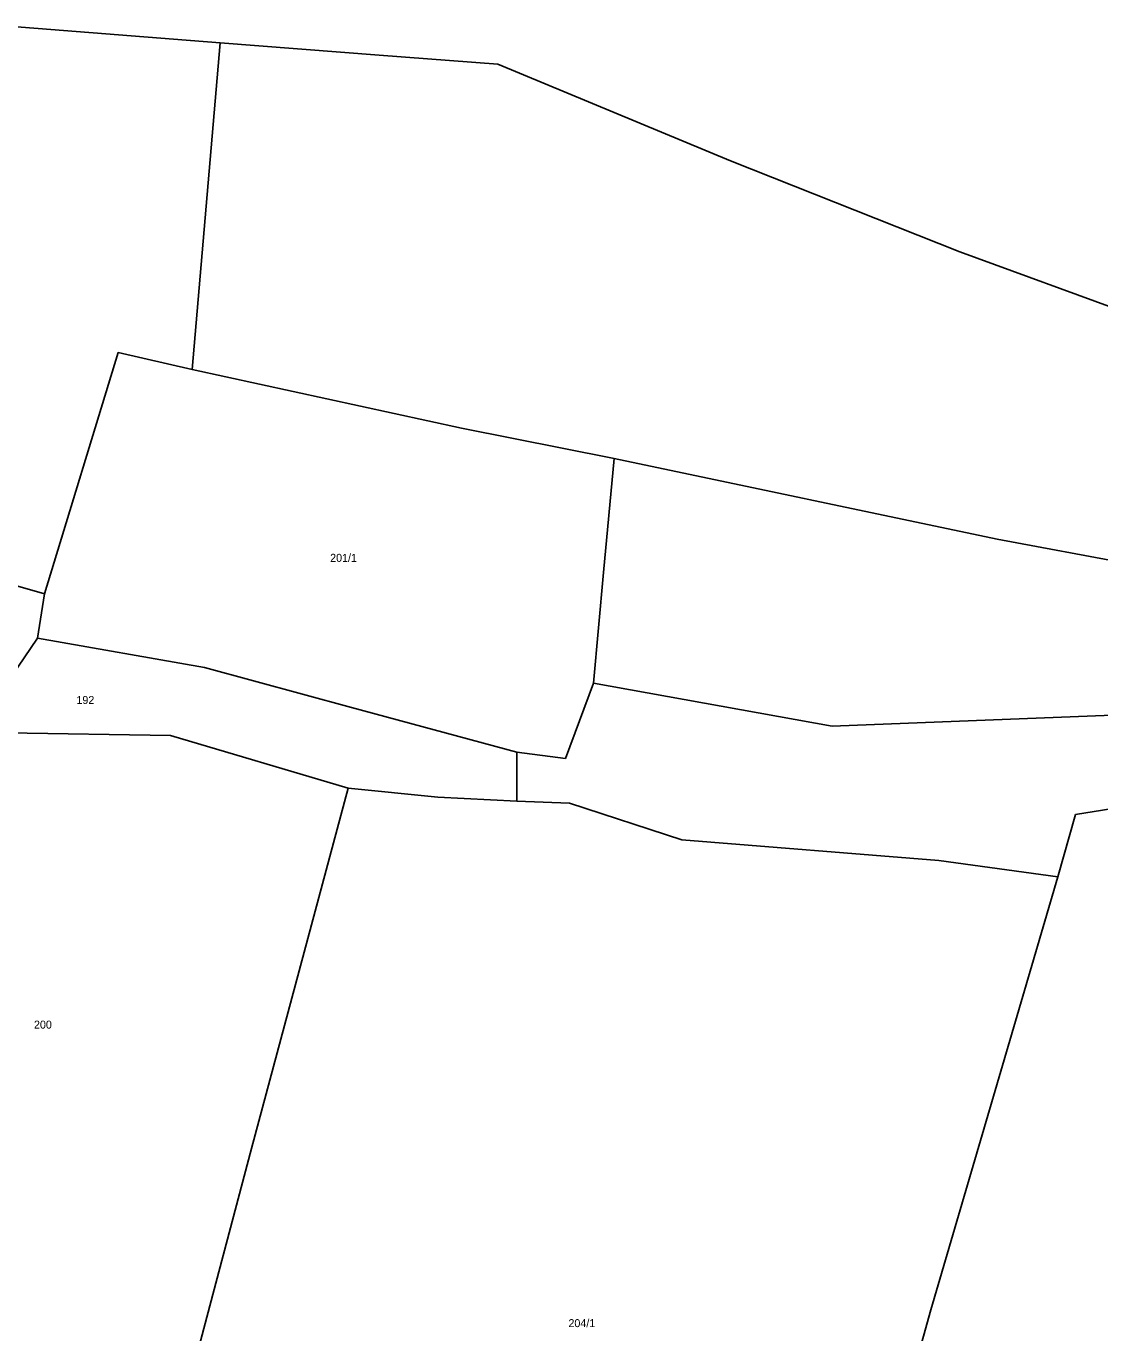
# Model space of a CAD drawing. Extents: x -791548 to -789311, y -1142631 to -1140855.
# Drawn here: x -790605.8 to -790377.8, y -1141528.8 to -1141251.3 of the extents above; entities that cross this region are included whole.
import ezdxf
from ezdxf.enums import TextEntityAlignment as Align

# ---------------------------------------------------------------- set-up
doc = ezdxf.new("R2010")
doc.units = 0
doc.header["$LTSCALE"] = 0.68
doc.layers.add('1', color=7, linetype='Continuous', lineweight=25)
doc.layers.add('2', color=7, linetype='Continuous')

msp = doc.modelspace()

# ---------------------------------------------------------------- linework, layer by layer
at = {"layer": '1'}
for p, q in [((-790574.52, -1141254.07), (-790609.55, -1141251.27)), ((-790574.52, -1141254.07), (-790564.64, -1141254.83)), ((-790570.59, -1141324.19), (-790564.64, -1141254.83)), ((-790564.64, -1141254.83), (-790530.84, -1141257.42)), ((-790505.62, -1141259.33), (-790530.84, -1141257.42)), ((-790456.26, -1141279.85), (-790505.62, -1141259.33)), ((-790407.51, -1141299.23), (-790456.26, -1141279.85)), ((-790322.4, -1141330.26), (-790407.51, -1141299.23)), ((-790601.94, -1141371.83), (-790586.26, -1141320.61)), ((-790586.26, -1141320.61), (-790570.59, -1141324.19)), ((-790513.36, -1141336.67), (-790570.59, -1141324.19)), ((-790480.92, -1141343.07), (-790513.36, -1141336.67)), ((-790483.19, -1141367.29), (-790480.92, -1141343.07)), ((-790399.6, -1141360.25), (-790480.92, -1141343.07)), ((-790335.65, -1141372.07), (-790399.6, -1141360.25)), ((-790601.94, -1141371.83), (-790626.13, -1141364.99)), ((-790485.29, -1141390.8), (-790483.19, -1141367.29)), ((-790603.44, -1141381.28), (-790601.94, -1141371.83)), ((-790611.73, -1141393.4), (-790603.44, -1141381.28)), ((-790567.95, -1141387.46), (-790603.44, -1141381.28)), ((-790536.74, -1141395.99), (-790567.95, -1141387.46)), ((-790491.26, -1141406.79), (-790485.29, -1141390.8)), ((-790485.29, -1141390.8), (-790434.62, -1141399.94)), ((-790501.59, -1141405.51), (-790536.74, -1141395.99)), ((-790434.62, -1141399.94), (-790344.25, -1141396.36)), ((-790609.89, -1141401.37), (-790575.13, -1141401.94)), ((-790575.13, -1141401.94), (-790537.46, -1141413.13)), ((-790501.6, -1141415.91), (-790501.59, -1141405.51)), ((-790501.59, -1141405.51), (-790491.26, -1141406.79)), ((-790557.94, -1141489.62), (-790537.46, -1141413.13)), ((-790537.46, -1141413.13), (-790518.37, -1141415.04)), ((-790518.37, -1141415.04), (-790501.6, -1141415.91)), ((-790490.42, -1141416.31), (-790501.6, -1141415.91)), ((-790466.55, -1141424.12), (-790490.42, -1141416.31)), ((-790369.23, -1141416.5), (-790382.93, -1141418.73)), ((-790382.93, -1141418.73), (-790386.72, -1141431.98)), ((-790412.01, -1141428.45), (-790466.55, -1141424.12)), ((-790386.72, -1141431.98), (-790412.01, -1141428.45)), ((-790413.68, -1141523.93), (-790386.72, -1141431.98)), ((-790578.57, -1141567.47), (-790557.94, -1141489.62)), ((-790451.05, -1141657.46), (-790413.68, -1141523.93))]:
    msp.add_line(p, q, dxfattribs=at)

# ---------------------------------------------------------------- texts
at = {"layer": '2'}
for s, p in [('201/1', (-790538.41, -1141365.052)), ('192', (-790593.249, -1141395.252)), ('200', (-790602.259, -1141464.192)), ('204/1', (-790487.8, -1141527.602))]:
    msp.add_text(s, height=1.7, dxfattribs=at).set_placement(p, align=Align.CENTER)

doc.saveas('drawing.dxf')
